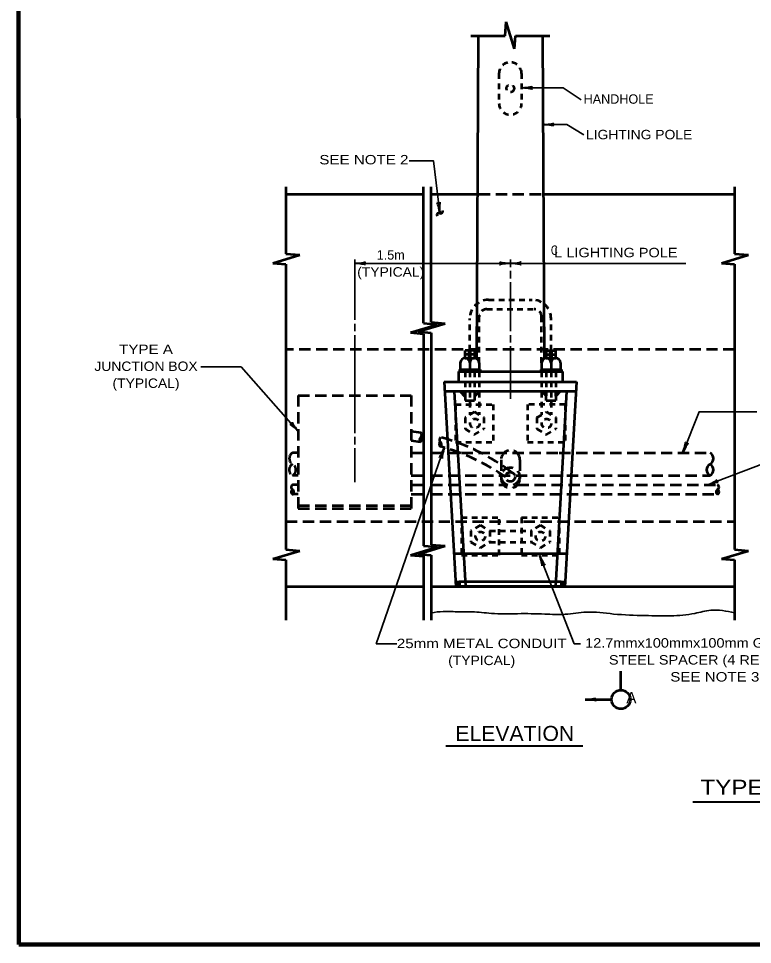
# Model space of a CAD drawing. Extents: x -35 to 821, y -23 to 522.
# Drawn here: x 22.7 to 256.3, y -10.9 to 283.7 of the extents above; entities that cross this region are included whole.
import ezdxf
from ezdxf.enums import TextEntityAlignment as Align

# ---------------------------------------------------------------- set-up
doc = ezdxf.new("R2010")
doc.units = 0
doc.header["$LTSCALE"] = 1.2
doc.linetypes.add('MEDIUM_DASHED', pattern=[4.5, 3, -1.5])
doc.linetypes.add('SHORT_DASHED', pattern=[2.7, 1.5, -1.2])
doc.layers.add('1', color=7, linetype='Continuous', lineweight=35)

msp = doc.modelspace()

# ---------------------------------------------------------------- linework, layer by layer
at = {"layer": '1', "lineweight": 53}
for p, q in [((177.571, 278.22), (177.959, 282.65)), ((180.553, 274.049), (177.959, 282.65)), ((166.645, 278.22), (177.571, 278.22)), ((169.045, 278.22), (168.44, 175.514)), ((180.553, 274.049), (180.918, 278.22)), ((180.918, 278.22), (191.845, 278.22)), ((189.445, 278.22), (190.049, 175.484)), ((107.845, 230.22), (107.845, 208.894)), ((151.645, 186.767), (151.645, 230.22)), ((154.045, 187.067), (154.045, 230.22)), ((250.645, 230.22), (250.645, 208.894)), ((107.845, 227.82), (151.645, 227.82)), ((154.045, 227.82), (169.195, 227.82)), ((189.295, 227.82), (250.645, 227.82)), ((103.673, 205.913), (112.274, 208.507)), ((107.845, 208.894), (112.274, 208.507)), ((246.473, 205.913), (255.074, 208.507)), ((250.645, 208.894), (255.074, 208.507)), ((103.673, 205.913), (107.845, 205.548)), ((107.845, 205.548), (107.845, 114.767)), ((246.473, 205.913), (250.645, 205.548)), ((250.645, 205.548), (250.645, 114.767)), ((147.473, 183.785), (156.074, 186.379)), ((149.873, 184.085), (158.474, 186.679)), ((151.645, 186.767), (156.074, 186.379)), ((154.045, 187.067), (158.474, 186.679)), ((147.473, 183.785), (151.645, 183.42)), ((149.873, 184.085), (154.045, 183.72)), ((151.645, 183.42), (151.645, 115.967)), ((154.045, 183.72), (154.045, 116.267)), ((164.836, 175.641), (164.836, 178.041)), ((167.845, 178.041), (164.836, 178.041)), ((167.845, 176.841), (164.836, 176.841)), ((166.945, 177.441), (165.736, 177.441)), ((167.845, 178.041), (167.845, 175.641)), ((190.645, 178.039), (193.716, 178.041)), ((190.645, 178.039), (190.645, 175.639)), ((190.645, 176.839), (193.716, 176.841)), ((191.544, 177.439), (192.816, 177.44)), ((193.716, 175.641), (193.716, 178.041)), ((163.336, 174.17), (163.336, 172.02)), ((164.836, 175.641), (167.845, 175.641)), ((164.836, 175.641), (167.845, 175.641)), ((166.945, 176.241), (165.736, 176.241)), ((166.336, 174.17), (166.336, 172.02)), ((169.336, 174.17), (169.336, 172.02)), ((189.216, 174.17), (189.216, 172.02)), ((190.645, 175.639), (193.716, 175.641)), ((190.645, 175.639), (193.716, 175.641)), ((191.545, 176.239), (192.817, 176.24)), ((192.216, 174.17), (192.216, 172.02)), ((195.216, 174.17), (195.216, 172.02)), ((162.736, 171.42), (170.836, 171.42)), ((162.736, 171.42), (162.736, 168.12)), ((163.036, 172.02), (169.636, 172.02)), ((163.036, 172.02), (163.036, 171.42)), ((169.636, 172.02), (169.636, 171.42)), ((170.836, 171.42), (187.716, 171.42)), ((187.716, 171.42), (195.816, 171.42)), ((188.916, 172.02), (195.516, 172.02)), ((188.916, 172.02), (188.916, 171.42)), ((195.516, 172.02), (195.516, 171.42)), ((195.816, 171.42), (195.816, 168.12)), ((158.234, 168.12), (200.317, 168.12)), ((158.234, 168.12), (161.96, 103.02)), ((158.406, 165.12), (166.036, 165.12)), ((161.414, 165.052), (164.959, 103.123)), ((164.836, 165.12), (164.836, 162.12)), ((166.036, 165.12), (170.545, 165.12)), ((167.845, 165.12), (167.845, 162.12)), ((190.645, 162.12), (190.645, 165.12)), ((197.137, 165.052), (193.593, 103.123)), ((193.716, 165.12), (193.716, 162.12)), ((164.836, 162.12), (167.845, 162.12)), ((190.645, 162.12), (193.716, 162.12)), ((147.745, 152.414), (150.73, 151.945)), ((147.745, 149.414), (150.599, 148.968)), ((147.473, 112.985), (156.074, 115.579)), ((149.873, 113.285), (158.474, 115.879)), ((151.645, 115.967), (156.074, 115.579)), ((154.045, 116.267), (158.474, 115.879)), ((103.673, 111.785), (112.274, 114.379)), ((107.845, 114.767), (112.274, 114.379)), ((147.473, 112.985), (151.645, 112.62)), ((149.873, 113.285), (154.045, 112.92)), ((151.645, 112.62), (151.645, 92.22)), ((154.045, 112.92), (154.045, 92.22)), ((161.359, 113.52), (197.193, 113.52)), ((246.473, 111.785), (255.074, 114.379)), ((250.645, 114.767), (255.074, 114.379)), ((103.673, 111.785), (107.845, 111.42)), ((107.845, 111.42), (107.845, 92.22)), ((246.473, 111.785), (250.645, 111.42)), ((250.645, 111.42), (250.645, 92.22)), ((161.895, 104.522), (161.981, 103.022)), ((161.933, 104.524), (162.019, 103.024)), ((161.955, 104.525), (162.041, 103.025)), ((161.977, 104.526), (162.063, 103.026)), ((161.998, 104.52), (161.998, 103.02)), ((162.005, 104.52), (162.005, 103.02)), ((162.02, 104.52), (162.02, 103.02)), ((162.049, 104.52), (162.049, 103.02)), ((162.049, 104.52), (162.049, 103.02)), ((162.064, 104.52), (162.064, 103.02)), ((162.064, 104.52), (162.064, 103.02)), ((162.086, 104.52), (162.086, 103.02)), ((162.093, 104.52), (162.093, 103.02)), ((162.108, 104.52), (162.108, 103.02)), ((162.123, 104.52), (162.123, 103.02)), ((162.137, 104.52), (162.137, 103.02)), ((162.152, 104.52), (162.152, 103.02)), ((162.167, 104.52), (162.167, 103.02)), ((162.167, 104.52), (162.167, 103.02)), ((162.174, 104.52), (162.174, 103.02)), ((162.181, 104.52), (162.181, 103.02)), ((162.196, 104.52), (162.196, 103.02)), ((162.203, 104.52), (162.203, 103.02)), ((162.203, 104.52), (162.203, 103.02)), ((162.203, 104.52), (162.203, 103.02)), ((162.233, 104.52), (162.233, 103.02)), ((162.247, 104.52), (162.247, 103.02)), ((162.255, 104.52), (162.255, 103.02)), ((162.255, 104.52), (162.255, 103.02)), ((162.277, 104.52), (162.277, 103.02)), ((162.284, 104.52), (162.284, 103.02)), ((162.284, 104.52), (162.284, 103.02)), ((162.299, 104.52), (162.299, 103.02)), ((162.313, 104.52), (162.313, 103.02)), ((162.313, 104.52), (162.313, 103.02)), ((162.343, 104.52), (162.343, 103.02)), ((162.365, 104.52), (162.365, 103.02)), ((162.365, 104.52), (162.365, 103.02)), ((162.387, 104.52), (162.387, 103.02)), ((162.416, 104.52), (162.416, 103.02)), ((162.431, 104.52), (162.431, 103.02)), ((162.431, 104.52), (162.431, 103.02)), ((162.453, 104.52), (162.453, 103.02)), ((162.49, 104.52), (162.49, 103.02)), ((162.497, 104.52), (162.497, 103.02)), ((162.519, 104.52), (162.519, 103.02)), ((162.548, 104.52), (162.548, 103.02)), ((162.57, 104.52), (162.57, 103.02)), ((162.57, 104.52), (162.57, 103.02)), ((162.578, 104.52), (162.578, 103.02)), ((162.578, 104.52), (162.578, 103.02)), ((162.585, 104.52), (162.585, 103.02)), ((162.621, 104.52), (162.621, 103.02)), ((162.644, 104.52), (162.644, 103.02)), ((162.651, 104.52), (162.651, 103.02)), ((162.673, 104.52), (162.673, 103.02)), ((162.688, 104.52), (162.688, 103.02)), ((162.702, 104.52), (162.702, 103.02)), ((162.732, 104.52), (162.732, 103.02)), ((162.739, 104.52), (162.739, 103.02)), ((162.761, 104.52), (162.761, 103.02)), ((162.79, 104.52), (162.79, 103.02)), ((162.798, 104.52), (162.798, 103.02)), ((162.798, 104.52), (162.798, 103.02)), ((162.812, 104.52), (162.812, 103.02)), ((162.827, 104.52), (162.827, 103.02)), ((162.849, 104.52), (162.849, 103.02)), ((162.856, 104.52), (162.856, 103.02)), ((162.864, 104.52), (162.864, 103.02)), ((162.878, 104.52), (162.878, 103.02)), ((162.886, 104.52), (162.886, 103.02)), ((162.915, 104.52), (162.915, 103.02)), ((162.922, 104.52), (162.922, 103.02)), ((162.93, 104.52), (162.93, 103.02)), ((162.937, 104.52), (162.937, 103.02)), ((162.959, 104.52), (162.959, 103.02)), ((162.966, 104.52), (162.966, 103.02)), ((162.988, 104.52), (162.988, 103.02)), ((163.003, 104.52), (163.003, 103.02)), ((163.01, 104.52), (163.01, 103.02)), ((163.025, 104.52), (163.025, 103.02)), ((163.047, 104.52), (163.047, 103.02)), ((163.054, 104.52), (163.054, 103.02)), ((163.054, 104.52), (163.054, 103.02)), ((163.054, 104.52), (163.054, 103.02)), ((163.084, 104.52), (163.084, 103.02)), ((163.084, 104.52), (163.084, 103.02)), ((195.462, 104.52), (195.462, 103.02)), ((195.475, 104.52), (195.475, 103.02)), ((195.501, 104.52), (195.501, 103.02)), ((195.507, 104.52), (195.507, 103.02)), ((195.532, 104.52), (195.532, 103.02)), ((195.551, 104.52), (195.551, 103.02)), ((195.551, 104.52), (195.551, 103.02)), ((195.558, 104.52), (195.558, 103.02)), ((195.564, 104.52), (195.564, 103.02)), ((195.57, 104.52), (195.57, 103.02)), ((195.57, 104.52), (195.57, 103.02)), ((195.589, 104.52), (195.589, 103.02)), ((195.621, 104.52), (195.621, 103.02)), ((195.621, 104.52), (195.621, 103.02)), ((195.627, 104.52), (195.627, 103.02)), ((195.659, 104.52), (195.659, 103.02)), ((195.672, 104.52), (195.672, 103.02)), ((195.672, 104.52), (195.672, 103.02)), ((195.678, 104.52), (195.678, 103.02)), ((195.691, 104.52), (195.691, 103.02)), ((195.697, 104.52), (195.697, 103.02)), ((195.704, 104.52), (195.704, 103.02)), ((195.71, 104.52), (195.71, 103.02)), ((195.71, 104.52), (195.71, 103.02)), ((195.742, 104.52), (195.742, 103.02)), ((195.761, 104.52), (195.761, 103.02)), ((195.761, 104.52), (195.761, 103.02)), ((195.78, 104.52), (195.78, 103.02)), ((195.786, 104.52), (195.786, 103.02)), ((195.792, 104.52), (195.792, 103.02)), ((195.799, 104.52), (195.799, 103.02)), ((195.799, 104.52), (195.799, 103.02)), ((195.818, 104.52), (195.818, 103.02)), ((195.837, 104.52), (195.837, 103.02)), ((195.85, 104.52), (195.85, 103.02)), ((195.875, 104.52), (195.875, 103.02)), ((195.894, 104.52), (195.894, 103.02)), ((195.9, 104.52), (195.9, 103.02)), ((195.9, 104.52), (195.9, 103.02)), ((195.907, 104.52), (195.907, 103.02)), ((195.913, 104.52), (195.913, 103.02)), ((195.913, 104.52), (195.913, 103.02)), ((195.926, 104.52), (195.926, 103.02)), ((195.945, 104.52), (195.945, 103.02)), ((195.964, 104.52), (195.964, 103.02)), ((195.964, 104.52), (195.964, 103.02)), ((195.989, 104.52), (195.989, 103.02)), ((195.989, 104.52), (195.989, 103.02)), ((195.989, 104.52), (195.989, 103.02)), ((196.002, 104.52), (196.002, 103.02)), ((196.021, 104.52), (196.021, 103.02)), ((196.027, 104.52), (196.027, 103.02)), ((196.059, 104.52), (196.059, 103.02)), ((196.065, 104.52), (196.065, 103.02)), ((196.065, 104.52), (196.065, 103.02)), ((196.078, 104.52), (196.078, 103.02)), ((196.091, 104.52), (196.091, 103.02)), ((196.103, 104.52), (196.103, 103.02)), ((196.116, 104.52), (196.116, 103.02)), ((196.123, 104.52), (196.123, 103.02)), ((196.123, 104.52), (196.123, 103.02)), ((196.123, 104.52), (196.123, 103.02)), ((196.142, 104.52), (196.142, 103.02)), ((196.161, 104.52), (196.161, 103.02)), ((196.167, 104.52), (196.167, 103.02)), ((196.192, 104.52), (196.192, 103.02)), ((196.211, 104.52), (196.211, 103.02)), ((196.211, 104.52), (196.211, 103.02)), ((196.23, 104.52), (196.23, 103.02)), ((196.237, 104.52), (196.237, 103.02)), ((196.237, 104.52), (196.237, 103.02)), ((196.256, 104.52), (196.256, 103.02)), ((196.288, 104.52), (196.288, 103.02)), ((196.307, 104.52), (196.307, 103.02)), ((196.307, 104.52), (196.307, 103.02)), ((196.326, 104.52), (196.326, 103.02)), ((196.332, 104.52), (196.332, 103.02)), ((196.345, 104.52), (196.345, 103.02)), ((196.357, 104.52), (196.357, 103.02)), ((196.376, 104.52), (196.376, 103.02)), ((196.395, 104.52), (196.395, 103.02)), ((196.415, 104.52), (196.415, 103.02)), ((196.415, 104.52), (196.415, 103.02)), ((196.415, 104.52), (196.415, 103.02)), ((196.44, 104.52), (196.44, 103.02)), ((196.459, 104.52), (196.459, 103.02)), ((196.465, 104.52), (196.465, 103.02)), ((196.472, 104.52), (196.472, 103.02)), ((196.478, 104.52), (196.478, 103.02)), ((196.491, 104.52), (196.491, 103.02)), ((196.503, 104.52), (196.503, 103.02)), ((196.503, 104.52), (196.503, 103.02)), ((196.516, 104.52), (196.516, 103.02)), ((196.529, 104.52), (196.529, 103.02)), ((196.535, 104.52), (196.535, 103.02)), ((196.535, 104.52), (196.535, 103.02)), ((196.643, 104.522), (196.557, 103.022)), ((196.651, 104.522), (196.565, 103.022)), ((196.658, 104.521), (196.572, 103.021)), ((196.573, 104.52), (196.573, 103.02)), ((196.667, 104.521), (196.582, 103.021)), ((107.845, 103.02), (151.645, 103.02)), ((214.457, 70.02), (214.457, 76.02)), ((203.057, 67.02), (211.457, 67.02))]:
    msp.add_line(p, q, dxfattribs=at)
at = {"layer": '1', "linetype": 'SHORT_DASHED', "lineweight": 53}
for p, q in [((175.645, 266.29), (175.645, 256.69)), ((182.845, 266.29), (182.845, 256.69)), ((172.336, 194.22), (186.216, 194.22)), ((169.336, 174.17), (169.336, 188.82)), ((171.736, 191.22), (186.816, 191.22)), ((189.216, 174.17), (189.216, 188.82)), ((166.336, 178.041), (166.336, 188.22)), ((192.216, 178.04), (192.216, 188.22)), ((164.836, 171.42), (164.836, 165.12)), ((166.336, 171.42), (166.336, 157.62)), ((167.845, 171.42), (167.845, 165.12)), ((169.336, 171.42), (169.336, 157.62)), ((189.216, 171.42), (189.216, 157.62)), ((190.645, 171.42), (190.645, 165.12)), ((192.216, 171.42), (192.216, 157.62)), ((193.716, 171.42), (193.716, 165.12)), ((161.836, 160.92), (161.836, 148.92)), ((161.836, 160.92), (173.836, 160.92)), ((173.836, 160.92), (173.836, 148.92)), ((184.716, 160.92), (184.716, 148.92)), ((196.716, 160.92), (184.716, 160.92)), ((196.716, 160.92), (196.716, 148.92)), ((167.836, 158.52), (164.836, 156.72)), ((164.836, 156.72), (164.836, 153.12)), ((167.836, 158.52), (170.836, 156.72)), ((170.836, 156.72), (170.836, 153.12)), ((187.716, 156.72), (187.716, 153.12)), ((193.716, 156.72), (193.716, 153.12)), ((161.836, 148.92), (173.836, 148.92)), ((184.716, 148.92), (196.716, 148.92)), ((163.713, 124.92), (175.713, 124.92)), ((163.713, 124.92), (163.713, 112.92)), ((182.838, 124.92), (194.838, 124.92)), ((182.838, 124.92), (182.838, 112.92)), ((194.838, 124.92), (194.838, 112.92)), ((194.838, 124.92), (194.838, 112.92)), ((169.713, 122.52), (166.713, 120.72)), ((169.713, 122.52), (172.713, 120.72)), ((188.838, 122.52), (185.838, 120.72)), ((188.838, 122.52), (191.838, 120.72)), ((166.713, 120.72), (166.713, 117.12)), ((172.713, 120.72), (172.713, 117.12)), ((172.713, 120.72), (185.838, 120.72)), ((185.838, 120.72), (185.838, 117.12)), ((191.838, 120.72), (191.838, 117.12)), ((172.713, 117.12), (185.838, 117.12)), ((182.838, 112.92), (194.838, 112.92))]:
    msp.add_line(p, q, dxfattribs=at)
at = {"layer": '1', "linetype": 'MEDIUM_DASHED', "lineweight": 53}
for p, q in [((169.195, 227.82), (189.295, 227.82)), ((250.645, 178.427), (107.845, 178.427)), ((111.745, 163.814), (147.745, 163.814)), ((111.745, 163.814), (111.745, 127.814)), ((147.745, 163.814), (147.745, 127.814)), ((111.745, 145.514), (109.945, 145.514)), ((147.745, 145.514), (151.645, 145.514)), ((176.317, 143.34), (176.317, 137.34)), ((182.317, 143.34), (182.317, 137.34)), ((111.745, 138.314), (109.945, 138.314)), ((147.745, 138.314), (151.645, 138.314)), ((154.045, 138.314), (242.822, 138.314)), ((111.745, 135.314), (109.945, 135.314)), ((147.745, 135.314), (151.645, 135.314)), ((154.045, 135.314), (177.105, 135.314)), ((181.53, 135.314), (245.238, 135.314)), ((111.745, 132.314), (109.945, 132.314)), ((147.745, 132.314), (151.645, 132.314)), ((154.045, 132.314), (245.238, 132.314)), ((111.745, 128.714), (147.745, 128.714)), ((111.745, 127.814), (147.745, 127.814)), ((107.845, 123.614), (250.645, 123.614))]:
    msp.add_line(p, q, dxfattribs=at)
at = {"layer": '1'}
for p, q in [((129.745, 207.014), (129.745, 187.814)), ((179.276, 204.614), (179.276, 207.014)), ((179.276, 201.014), (179.276, 203.414)), ((179.276, 184.214), (179.276, 199.814)), ((129.745, 186.614), (129.745, 184.214)), ((129.745, 183.014), (129.745, 151.814)), ((179.276, 180.614), (179.276, 183.014)), ((179.276, 162.72), (179.276, 179.414)), ((129.745, 150.614), (129.745, 148.214)), ((129.745, 147.014), (129.745, 136.214)), ((158.248, 147.163), (136.578, 84.76)), ((161.874, 104.52), (196.678, 104.52)), ((143.144, 84.76), (136.578, 84.76))]:
    msp.add_line(p, q, dxfattribs=at)
at = {"layer": '1', "lineweight": 40}
for p, q in [((158.775, 52.284), (202.338, 52.284)), ((237.33, 34.43), (365.518, 34.43))]:
    msp.add_line(p, q, dxfattribs=at)
at = {"layer": '1', "lineweight": 158}
msp.add_line((814.415, -10.947), (22.815, -10.947), dxfattribs=at)
msp.add_lwpolyline([(814.415, 515.153), (22.715, 515.053), (22.815, -10.947)], dxfattribs=at)
at = {"layer": '1'}
for points in [[(182.823, 261.685), (196.084, 261.685), (201.843, 257.847)], [(189.611, 249.989), (197.248, 249.989), (202.624, 246.718)], [(156.815, 221.764), (154.773, 238.486), (147.082, 238.486)], [(129.745, 205.814), (179.276, 205.814), (235.14, 205.814)], [(111.745, 152.34), (93.53, 172.937), (80.781, 172.937)], [(234.119, 145.514), (239.348, 158.589), (257.675, 158.589)], [(242.039, 135.314), (259.667, 142.05), (263.201, 142.05)], [(188.565, 112.92), (199.607, 84.76), (201.589, 84.76)]]:
    msp.add_lwpolyline(points, dxfattribs=at)
at = {"layer": '1', "lineweight": 53}
for points in [[(200.317, 168.12), (196.678, 104.52), (196.592, 103.02)], [(170.545, 165.12), (189.445, 165.12), (192.516, 165.12), (200.146, 165.12)], [(154.045, 103.02), (195.476, 103.02), (250.645, 103.02)]]:
    msp.add_lwpolyline(points, dxfattribs=at)
for points in [[(189.142, 165.116), (190.642, 165.116), (190.642, 163.616)], [(193.741, 165.097), (195.241, 165.097), (193.741, 163.597)], [(164.761, 164.993), (163.261, 164.993), (164.761, 163.493)], [(167.897, 163.493), (169.397, 164.993), (167.897, 164.993)], [(195.476, 104.52), (195.476, 103.02), (163.076, 103.02), (163.076, 104.52)]]:
    msp.add_lwpolyline(points, close=True, dxfattribs=at)
at = {"layer": '1', "linetype": 'SHORT_DASHED', "lineweight": 53}
for points in [[(187.716, 156.72), (190.716, 158.52), (193.716, 156.72)], [(164.836, 153.12), (167.836, 151.32), (170.836, 153.12)], [(187.716, 153.12), (190.716, 151.32), (193.716, 153.12)], [(163.713, 112.92), (175.713, 112.92), (175.713, 124.92)], [(166.713, 117.12), (169.713, 115.32), (172.713, 117.12)], [(185.838, 117.12), (188.838, 115.32), (191.838, 117.12)]]:
    msp.add_lwpolyline(points, dxfattribs=at)
at = {"layer": '1', "linetype": 'MEDIUM_DASHED', "lineweight": 53}
msp.add_lwpolyline([(154.045, 145.514), (163.735, 145.514), (194.817, 145.514), (242.822, 145.514)], dxfattribs=at)
at = {"layer": '1', "linetype": 'SHORT_DASHED', "lineweight": 53}
for centre, radius in [((179.245, 261.49), 1.2), ((167.973, 154.878), 1.5), ((190.748, 154.835), 1.5), ((169.713, 118.92), 1.5), ((188.838, 118.92), 1.5)]:
    msp.add_circle(centre, radius, dxfattribs=at)
at = {"layer": '1', "linetype": 'MEDIUM_DASHED', "lineweight": 53}
for centre, radius in [((179.272, 138.003), 2.88), ((179.252, 137.865), 1.5)]:
    msp.add_circle(centre, radius, dxfattribs=at)
at = {"layer": '1', "lineweight": 53}
msp.add_circle((214.457, 67.02), 3, dxfattribs=at)
at = {"layer": '1', "linetype": 'SHORT_DASHED', "lineweight": 53}
for centre, radius, start, end in [((179.245, 266.218), 3.601, 1.1523, 178.8477), ((179.245, 256.762), 3.601, 181.1523, 358.8477), ((172.336, 188.22), 6, 90, 180), ((186.216, 188.22), 6, 0, 90), ((171.736, 188.82), 2.4, 90, 180), ((186.816, 188.82), 2.4, 0, 90)]:
    msp.add_arc(centre, radius, start, end, dxfattribs=at)
at = {"layer": '1', "lineweight": 53}
for centre, radius, start, end in [((156.505, 221.233), 0.615, 59.71531, 214.28469), ((157.126, 222.295), 0.615, 239.71531, 34.28469), ((164.836, 174.14), 1.5, 90, 178.88668), ((164.836, 174.14), 1.5, 1.11332, 90), ((164.836, 174.14), 1.5, 1.11332, 90), ((167.836, 174.14), 1.5, 89.67156, 178.88668), ((167.836, 174.14), 1.5, 90.32844, 178.88668), ((167.836, 174.14), 1.5, 1.11332, 89.67156), ((190.716, 174.14), 1.5, 92.7125, 178.88668), ((190.716, 174.14), 1.5, 1.11332, 92.7125), ((190.716, 174.14), 1.5, 1.11332, 87.2875), ((193.716, 174.14), 1.5, 90, 178.88668), ((193.716, 174.14), 1.5, 90, 178.88668), ((193.716, 174.14), 1.5, 1.11332, 90), ((151.386, 149.632), 1.014, 125.75502, 221.12003), ((150.019, 149.8), 1.014, 304.87997, 40.24498), ((150.074, 151.171), 1.014, 315.16746, 49.69352), ((157.689, 149.739), 1.014, 130.30648, 224.83254), ((157.411, 148.325), 0.827, 122.29232, 252.58274), ((156.377, 148.201), 1.014, 318.87997, 54.24498), ((241.799, 143.714), 2.07, 299.59893, 60.40107), ((243.764, 140.114), 2.031, 117.62202, 242.37798), ((241.901, 140.114), 2.022, 297.09451, 62.90548), ((245.635, 133.064), 0.852, 118.29957, 241.70043), ((244.834, 134.564), 0.852, 298.29957, 61.70043), ((244.834, 133.064), 0.852, 298.29957, 61.70043)]:
    msp.add_arc(centre, radius, start, end, dxfattribs=at)
at = {"layer": '1', "linetype": 'MEDIUM_DASHED', "lineweight": 53}
for centre, radius, start, end in [((138.718, 84.658), 68.354, 53.08802, 74.45884), ((138.718, 81.658), 68.354, 55.17394, 74.40337), ((110.967, 143.714), 2.07, 119.59892, 240.40107), ((179.317, 143.34), 3, 0, 180), ((110.865, 140.114), 2.022, 117.09452, 242.90549), ((109.003, 140.114), 2.031, 297.62202, 62.37798), ((179.317, 137.34), 3, 180, 0), ((110.348, 134.564), 0.852, 118.29957, 241.70043), ((110.348, 133.064), 0.852, 118.29957, 241.70043), ((109.548, 133.064), 0.852, 298.29957, 61.70043)]:
    msp.add_arc(centre, radius, start, end, dxfattribs=at)
at = {"layer": '1', "lineweight": 40}
for centre, major_axis, ratio, start_param, end_param in [((184.168, 261.431), (-2.108, 0.211), 0.07063, 3.1407148, 5.41811), ((184.133, 262.017), (-2.143, -0.187), 0.122415, 0.8963533, 3.1415927), ((190.92, 250.321), (-2.143, -0.187), 0.122415, 0.8963533, 3.1415927), ((190.955, 249.735), (-2.108, 0.211), 0.07063, 3.1407148, 5.41811), ((156.328, 223.023), (0.446, -2.104), 0.122415, 0.8963533, 3.1415927), ((156.904, 223.129), (0.046, -2.118), 0.07063, 3.1407148, 5.41811), ((131.054, 206.145), (-2.143, -0.187), 0.122415, 0.8963533, 3.1415927), ((131.054, 206.145), (-2.143, -0.187), 0.122415, 0.8963533, 3.1415927), ((177.931, 206.068), (2.108, -0.211), 0.07063, 3.1407148, 5.41811), ((177.931, 206.068), (2.108, -0.211), 0.07063, 3.1407148, 5.41811), ((180.585, 206.145), (-2.143, -0.187), 0.122415, 0.8963533, 3.1415927), ((131.089, 205.56), (-2.108, 0.211), 0.07063, 3.1407148, 5.41811), ((131.089, 205.56), (-2.108, 0.211), 0.07063, 3.1407148, 5.41811), ((177.966, 205.482), (2.143, 0.187), 0.122415, 0.8963533, 3.1415927), ((177.966, 205.482), (2.143, 0.187), 0.122415, 0.8963533, 3.1415927), ((180.62, 205.56), (-2.108, 0.211), 0.07063, 3.1407148, 5.41811), ((110.629, 153.101), (1.56, -1.481), 0.122415, 0.8963533, 3.1415927), ((111.044, 153.515), (-1.238, 1.719), 0.07063, 6.2823074, 8.5597026), ((234.298, 146.853), (-0.622, -2.059), 0.122415, 0.8963533, 3.1415927), ((234.854, 146.668), (0.978, 1.879), 0.07063, 6.2823074, 8.5597026), ((157.567, 145.976), (-0.891, -1.922), 0.07063, 6.2823074, 8.5597026), ((158.131, 145.817), (0.526, 2.086), 0.122415, 0.8963533, 3.1415927), ((243.144, 136.091), (-1.935, -0.94), 0.122415, 0.8963533, 3.1415927), ((243.386, 135.556), (2.044, 0.556), 0.07063, 6.2823074, 8.5597026), ((188.819, 111.576), (0.573, -2.039), 0.07063, 6.2823074, 8.5597026), ((189.352, 111.822), (-0.957, 1.927), 0.122415, 0.8963533, 3.1415927), ((204.402, 67.274), (-2.108, -0.211), 0.07063, 0.8650754, 3.1424706), ((204.367, 66.689), (-2.143, 0.187), 0.122415, 3.1415927, 5.386832)]:
    msp.add_ellipse(centre, major_axis=major_axis, ratio=ratio, start_param=start_param, end_param=end_param, dxfattribs=at)
at = {"layer": '1'}
msp.add_spline([(154.045, 94.62), (157.873, 95.022), (162.953, 94.923), (167.037, 94.923), (173.212, 94.425), (181.578, 94.325), (190.244, 94.225), (196.718, 94.126), (203.491, 94.823), (212.057, 94.225), (222.216, 93.727), (230.384, 93.627), (237.953, 94.425), (243.033, 95.421), (250.645, 94.62)], degree=3, dxfattribs=at)

# ---------------------------------------------------------------- texts
for s, height, p in [('HANDHOLE', 3, (202.58, 256.614)), ('A', 3.6, (216.177, 65.803))]:
    msp.add_text(s, height=height, dxfattribs=at).set_placement(p)
for s, height, width, p in [('LIGHTING POLE', 3, 1.1, (203.334, 245.305)), ('SEE NOTE 2', 3, 1.2, (118.467, 237.313)), ('C', 3, 0.75, (192.179, 208.512)), ('L LIGHTING POLE', 3, 1.15, (193.234, 207.758)), ('ELEVATION', 4.8, 1.05, (161.755, 53.823)), ('TYPE D - INSTALLATION DETAILS', 4.8, 1.2, (239.756, 36.684))]:
    msp.add_text(s, height=height, dxfattribs=dict(at, width=width)).set_placement(p)
msp.add_text('1.5m', height=3, dxfattribs=at).set_placement((141.188, 206.998), align=Align.CENTER)
for s, width, p in [('(TYPICAL)', 1.1, (141.188, 201.598)), ('TYPE A', 1.2, (63.296, 176.976)), ('JUNCTION BOX', 1.1, (63.296, 171.576)), ('(TYPICAL)', 1.1, (63.296, 166.176)), ('25mm METAL CONDUIT', 1.2, (170.142, 83.359)), ('12.7mmx100mmx100mm GALVANIZED', 1.15, (244.339, 83.533)), ('(TYPICAL)', 1.1, (170.142, 77.959)), ('STEEL SPACER (4 REQUIRED)', 1.15, (244.339, 78.133)), ('SEE NOTE 3', 1.2, (244.339, 72.733))]:
    msp.add_text(s, height=3, dxfattribs=dict(at, width=width)).set_placement(p, align=Align.CENTER)

doc.saveas('drawing.dxf')
